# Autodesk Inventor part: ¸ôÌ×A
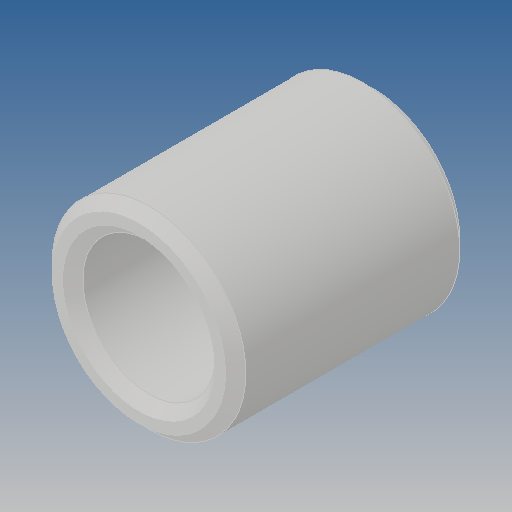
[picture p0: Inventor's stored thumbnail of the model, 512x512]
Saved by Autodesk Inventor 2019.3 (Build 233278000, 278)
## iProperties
Created: 2017-08
Part Number: ¸ôÌ×A
Material: Ogólny
Document SubType Name: Modeling
Designer: Admin
Density: 1 g/cm^3
Appearance: Domyślna
Author: Admin
Revision Number: ÈÎºÎ
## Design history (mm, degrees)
feature "ÊäÈë1"
node "Bryła1"
